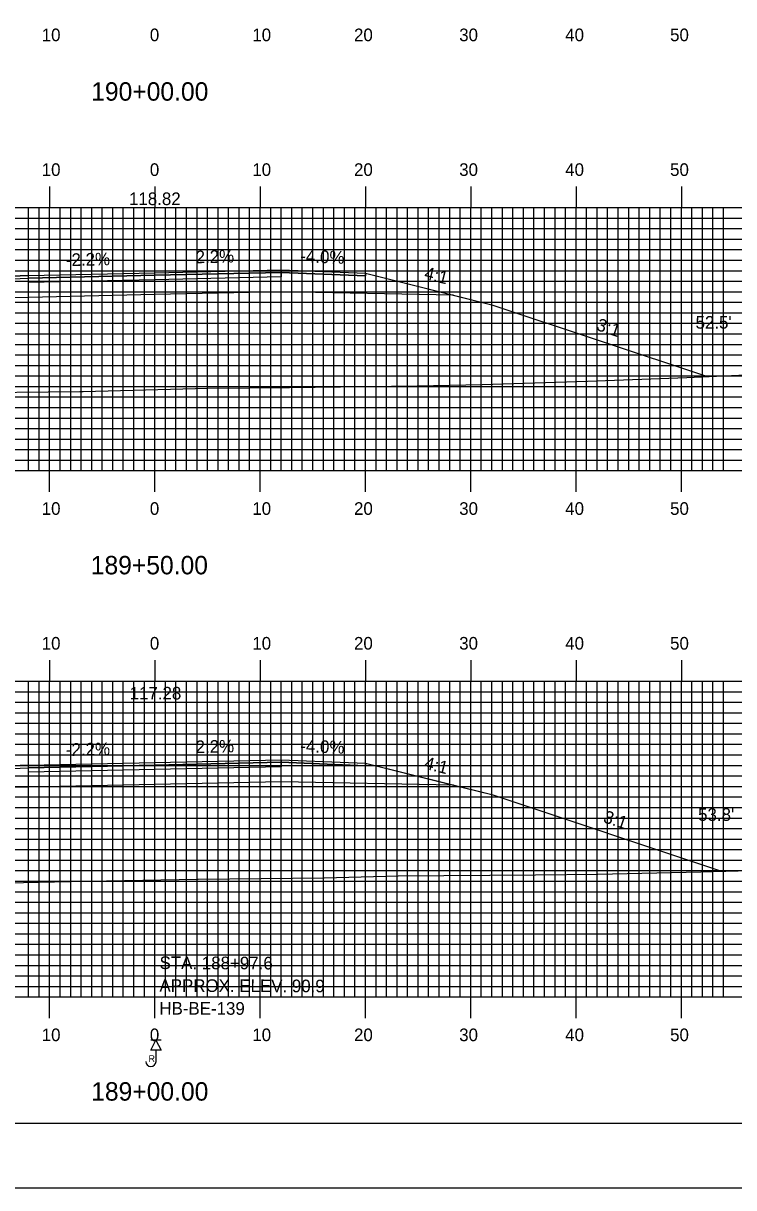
# Model space of a CAD drawing. Extents: x 1788156 to 1788500, y 442591 to 442811.
# Drawn here: x 1788309.6 to 1788377.1, y 442590.5 to 442701.2 of the extents above; entities that cross this region are included whole.
import ezdxf

# ---------------------------------------------------------------- set-up
doc = ezdxf.new("R2010")
doc.units = 0
for name, color, linetype in [('ANNOTATION', 7, 'Continuous'), ('BORDER', 7, 'Continuous'), ('BORING - NO REFUSAL', 7, 'Continuous'), ('BORING - REFUSAL', 7, 'Continuous'), ('D_Roadway_Centerline', 7, 'Continuous'), ('D_Roadway_Centerline_Text', 7, 'Continuous'), ('D_Roadway_Edge_Shoulder', 7, 'Continuous'), ('D_Roadway_Edge_TW', 7, 'Continuous'), ('D_Roadway_Pavement', 7, 'Continuous'), ('D_Roadway_SlopeLines', 7, 'Continuous'), ('D_Roadway_SubGrade', 7, 'Continuous'), ('D_Text_Standard', 7, 'Continuous'), ('H_V ANNOTATION', 7, 'Continuous'), ('MAJOR', 7, 'Continuous'), ('MINOR', 7, 'Continuous'), ('PLOT BOUNDARY', 7, 'Continuous'), ('S_Roadway_Centerline', 7, 'Continuous')]:
    doc.layers.add(name, color=color, linetype=linetype)

msp = doc.modelspace()

# ---------------------------------------------------------------- linework, layer by layer
at = {"layer": 'BORDER'}
msp.add_lwpolyline([(1788172.53, 442596.67), (1788492.53, 442596.67), (1788492.53, 442806.67), (1788172.53, 442806.67)], close=True, dxfattribs=at)
at = {"layer": 'BORING - NO REFUSAL'}
for p, q in [((1788322.71, 442604.57), (1788321.75, 442604.57)), ((1788322.23, 442603.61), (1788322.23, 442602.55))]:
    msp.add_line(p, q, dxfattribs=at)
msp.add_lwpolyline([(1788322.23, 442604.57), (1788322.71, 442603.61), (1788321.75, 442603.61)], close=True, dxfattribs=at)
msp.add_arc((1788321.75, 442602.55), 0.485, 180, 0, dxfattribs=at)
at = {"layer": 'D_Roadway_Centerline'}
for points in [[(1788265.27, 442665.61), (1788290.13, 442673.9), (1788293.77, 442674.81), (1788302.13, 442676.9), (1788310.13, 442677.22), (1788322.13, 442677.48), (1788334.13, 442677.75), (1788342.13, 442677.43), (1788350.49, 442675.33), (1788354.13, 442674.43), (1788374.61, 442667.6)], [(1788265.16, 442619.03), (1788290.13, 442627.36), (1788293.77, 442628.27), (1788302.13, 442630.36), (1788310.13, 442630.68), (1788322.13, 442630.94), (1788334.13, 442631.21), (1788342.13, 442630.89), (1788350.49, 442628.8), (1788354.13, 442627.89), (1788375.93, 442620.62)]]:
    msp.add_lwpolyline(points, dxfattribs=at)
at = {"layer": 'D_Roadway_Edge_Shoulder'}
for points in [[(1788310.13, 442677.22), (1788302.13, 442676.9), (1788302.13, 442676.65), (1788310.13, 442676.97)], [(1788334.13, 442677.75), (1788342.13, 442677.43), (1788342.13, 442677.18), (1788334.13, 442677.5)], [(1788310.13, 442630.68), (1788302.13, 442630.36), (1788302.13, 442630.11), (1788310.13, 442630.43)], [(1788334.13, 442631.21), (1788342.13, 442630.89), (1788342.13, 442630.64), (1788334.13, 442630.96)]]:
    msp.add_lwpolyline(points, close=True, dxfattribs=at)
at = {"layer": 'D_Roadway_Edge_TW'}
for points in [[(1788310.13, 442676.97), (1788310.13, 442677.22), (1788322.13, 442677.48), (1788334.13, 442677.75), (1788334.13, 442677.5), (1788322.13, 442677.23)], [(1788310.13, 442630.43), (1788310.13, 442630.68), (1788322.13, 442630.94), (1788334.13, 442631.21), (1788334.13, 442630.96), (1788322.13, 442630.69)]]:
    msp.add_lwpolyline(points, close=True, dxfattribs=at)
at = {"layer": 'D_Roadway_Pavement'}
for points in [[(1788310.13, 442676.55), (1788310.13, 442676.97), (1788322.13, 442677.23), (1788334.13, 442677.5), (1788334.13, 442677.08), (1788322.13, 442676.81)], [(1788310.13, 442630.01), (1788310.13, 442630.43), (1788322.13, 442630.69), (1788334.13, 442630.96), (1788334.13, 442630.54), (1788322.13, 442630.27)]]:
    msp.add_lwpolyline(points, close=True, dxfattribs=at)
at = {"layer": 'D_Roadway_SlopeLines'}
for points in [[(1788342.13, 442677.43), (1788354.13, 442674.43), (1788374.61, 442667.6)], [(1788342.13, 442630.89), (1788354.13, 442627.89), (1788375.93, 442620.62)]]:
    msp.add_lwpolyline(points, dxfattribs=at)
at = {"layer": 'D_Roadway_SubGrade'}
for points in [[(1788310.13, 442675.13), (1788293.77, 442674.81), (1788302.13, 442676.9), (1788302.13, 442676.65), (1788310.13, 442676.97), (1788322.13, 442677.23), (1788334.13, 442677.5), (1788342.13, 442677.18), (1788342.13, 442677.43), (1788350.49, 442675.33), (1788334.13, 442675.66), (1788322.13, 442675.4)], [(1788310.13, 442628.59), (1788293.77, 442628.27), (1788302.13, 442630.36), (1788302.13, 442630.11), (1788310.13, 442630.43), (1788322.13, 442630.69), (1788334.13, 442630.96), (1788342.13, 442630.64), (1788342.13, 442630.89), (1788350.49, 442628.8), (1788334.13, 442629.12), (1788322.13, 442628.86)]]:
    msp.add_lwpolyline(points, close=True, dxfattribs=at)
at = {"layer": 'MAJOR'}
for p, q in [((1788312.13, 442685.67), (1788312.13, 442683.67)), ((1788322.13, 442685.67), (1788322.13, 442683.67)), ((1788332.13, 442685.67), (1788332.13, 442683.67)), ((1788342.13, 442685.67), (1788342.13, 442683.67)), ((1788352.13, 442685.67), (1788352.13, 442683.67)), ((1788362.13, 442685.67), (1788362.13, 442683.67)), ((1788372.13, 442685.67), (1788372.13, 442683.67)), ((1788182.13, 442683.67), (1788462.13, 442683.67)), ((1788182.13, 442683.67), (1788462.13, 442683.67)), ((1788312.13, 442658.67), (1788312.13, 442683.67)), ((1788322.13, 442658.67), (1788322.13, 442683.67)), ((1788332.13, 442658.67), (1788332.13, 442683.67)), ((1788342.13, 442658.67), (1788342.13, 442683.67)), ((1788352.13, 442658.67), (1788352.13, 442683.67)), ((1788362.13, 442658.67), (1788362.13, 442683.67)), ((1788372.13, 442658.67), (1788372.13, 442683.67)), ((1788182.13, 442678.67), (1788462.13, 442678.67)), ((1788182.13, 442673.67), (1788462.13, 442673.67)), ((1788182.13, 442668.67), (1788462.13, 442668.67)), ((1788182.13, 442663.67), (1788462.13, 442663.67)), ((1788182.13, 442658.67), (1788462.13, 442658.67)), ((1788182.13, 442658.67), (1788462.13, 442658.67)), ((1788312.13, 442656.66), (1788312.13, 442658.67)), ((1788322.13, 442656.66), (1788322.13, 442658.67)), ((1788332.13, 442656.66), (1788332.13, 442658.67)), ((1788342.13, 442656.66), (1788342.13, 442658.67)), ((1788352.13, 442656.66), (1788352.13, 442658.67)), ((1788362.13, 442656.66), (1788362.13, 442658.67)), ((1788372.13, 442656.66), (1788372.13, 442658.67)), ((1788312.13, 442640.67), (1788312.13, 442638.67)), ((1788322.13, 442640.67), (1788322.13, 442638.67)), ((1788332.13, 442640.67), (1788332.13, 442638.67)), ((1788342.13, 442640.67), (1788342.13, 442638.67)), ((1788352.13, 442640.67), (1788352.13, 442638.67)), ((1788362.13, 442640.67), (1788362.13, 442638.67)), ((1788372.13, 442640.67), (1788372.13, 442638.67)), ((1788182.13, 442638.67), (1788462.13, 442638.67)), ((1788182.13, 442638.67), (1788462.13, 442638.67)), ((1788312.13, 442608.67), (1788312.13, 442638.67)), ((1788322.13, 442608.67), (1788322.13, 442638.67)), ((1788332.13, 442608.67), (1788332.13, 442638.67)), ((1788342.13, 442608.67), (1788342.13, 442638.67)), ((1788352.13, 442608.67), (1788352.13, 442638.67)), ((1788362.13, 442608.67), (1788362.13, 442638.67)), ((1788372.13, 442608.67), (1788372.13, 442638.67)), ((1788182.13, 442633.67), (1788462.13, 442633.67)), ((1788182.13, 442628.67), (1788462.13, 442628.67)), ((1788182.13, 442623.67), (1788462.13, 442623.67)), ((1788182.13, 442618.67), (1788462.13, 442618.67)), ((1788182.13, 442613.67), (1788462.13, 442613.67)), ((1788182.13, 442608.67), (1788462.13, 442608.67)), ((1788182.13, 442608.67), (1788462.13, 442608.67)), ((1788312.13, 442606.66), (1788312.13, 442608.67)), ((1788322.13, 442606.66), (1788322.13, 442608.67)), ((1788332.13, 442606.66), (1788332.13, 442608.67)), ((1788342.13, 442606.66), (1788342.13, 442608.67)), ((1788352.13, 442606.66), (1788352.13, 442608.67)), ((1788362.13, 442606.66), (1788362.13, 442608.67)), ((1788372.13, 442606.66), (1788372.13, 442608.67))]:
    msp.add_line(p, q, dxfattribs=at)
at = {"layer": 'MINOR'}
for p, q in [((1788310.13, 442658.67), (1788310.13, 442683.67)), ((1788311.13, 442658.67), (1788311.13, 442683.67)), ((1788313.13, 442658.67), (1788313.13, 442683.67)), ((1788314.13, 442658.67), (1788314.13, 442683.67)), ((1788315.13, 442658.67), (1788315.13, 442683.67)), ((1788316.13, 442658.67), (1788316.13, 442683.67)), ((1788317.13, 442658.67), (1788317.13, 442683.67)), ((1788318.13, 442658.67), (1788318.13, 442683.67)), ((1788319.13, 442658.67), (1788319.13, 442683.67)), ((1788320.13, 442658.67), (1788320.13, 442683.67)), ((1788321.13, 442658.67), (1788321.13, 442683.67)), ((1788323.13, 442658.67), (1788323.13, 442683.67)), ((1788324.13, 442658.67), (1788324.13, 442683.67)), ((1788325.13, 442658.67), (1788325.13, 442683.67)), ((1788326.13, 442658.67), (1788326.13, 442683.67)), ((1788327.13, 442658.67), (1788327.13, 442683.67)), ((1788328.13, 442658.67), (1788328.13, 442683.67)), ((1788329.13, 442658.67), (1788329.13, 442683.67)), ((1788330.13, 442658.67), (1788330.13, 442683.67)), ((1788331.13, 442658.67), (1788331.13, 442683.67)), ((1788333.13, 442658.67), (1788333.13, 442683.67)), ((1788334.13, 442658.67), (1788334.13, 442683.67)), ((1788335.13, 442658.67), (1788335.13, 442683.67)), ((1788336.13, 442658.67), (1788336.13, 442683.67)), ((1788337.13, 442658.67), (1788337.13, 442683.67)), ((1788338.13, 442658.67), (1788338.13, 442683.67)), ((1788339.13, 442658.67), (1788339.13, 442683.67)), ((1788340.13, 442658.67), (1788340.13, 442683.67)), ((1788341.13, 442658.67), (1788341.13, 442683.67)), ((1788343.13, 442658.67), (1788343.13, 442683.67)), ((1788344.13, 442658.67), (1788344.13, 442683.67)), ((1788345.13, 442658.67), (1788345.13, 442683.67)), ((1788346.13, 442658.67), (1788346.13, 442683.67)), ((1788347.13, 442658.67), (1788347.13, 442683.67)), ((1788348.13, 442658.67), (1788348.13, 442683.67)), ((1788349.13, 442658.67), (1788349.13, 442683.67)), ((1788350.13, 442658.67), (1788350.13, 442683.67)), ((1788351.13, 442658.67), (1788351.13, 442683.67)), ((1788353.13, 442658.67), (1788353.13, 442683.67)), ((1788354.13, 442658.67), (1788354.13, 442683.67)), ((1788355.13, 442658.67), (1788355.13, 442683.67)), ((1788356.13, 442658.67), (1788356.13, 442683.67)), ((1788357.13, 442658.67), (1788357.13, 442683.67)), ((1788358.13, 442658.67), (1788358.13, 442683.67)), ((1788359.13, 442658.67), (1788359.13, 442683.67)), ((1788360.13, 442658.67), (1788360.13, 442683.67)), ((1788361.13, 442658.67), (1788361.13, 442683.67)), ((1788363.13, 442658.67), (1788363.13, 442683.67)), ((1788364.13, 442658.67), (1788364.13, 442683.67)), ((1788365.13, 442658.67), (1788365.13, 442683.67)), ((1788366.13, 442658.67), (1788366.13, 442683.67)), ((1788367.13, 442658.67), (1788367.13, 442683.67)), ((1788368.13, 442658.67), (1788368.13, 442683.67)), ((1788369.13, 442658.67), (1788369.13, 442683.67)), ((1788370.13, 442658.67), (1788370.13, 442683.67)), ((1788371.13, 442658.67), (1788371.13, 442683.67)), ((1788373.13, 442658.67), (1788373.13, 442683.67)), ((1788374.13, 442658.67), (1788374.13, 442683.67)), ((1788375.13, 442658.67), (1788375.13, 442683.67)), ((1788376.13, 442658.67), (1788376.13, 442683.67)), ((1788182.13, 442682.67), (1788462.13, 442682.67)), ((1788182.13, 442681.67), (1788462.13, 442681.67)), ((1788182.13, 442680.67), (1788462.13, 442680.67)), ((1788182.13, 442679.67), (1788462.13, 442679.67)), ((1788182.13, 442677.67), (1788462.13, 442677.67)), ((1788182.13, 442676.67), (1788462.13, 442676.67)), ((1788182.13, 442675.67), (1788462.13, 442675.67)), ((1788182.13, 442674.67), (1788462.13, 442674.67)), ((1788182.13, 442672.67), (1788462.13, 442672.67)), ((1788182.13, 442671.67), (1788462.13, 442671.67)), ((1788182.13, 442670.67), (1788462.13, 442670.67)), ((1788182.13, 442669.67), (1788462.13, 442669.67)), ((1788182.13, 442667.67), (1788462.13, 442667.67)), ((1788182.13, 442666.67), (1788462.13, 442666.67)), ((1788182.13, 442665.67), (1788462.13, 442665.67)), ((1788182.13, 442664.67), (1788462.13, 442664.67)), ((1788182.13, 442662.67), (1788462.13, 442662.67)), ((1788182.13, 442661.67), (1788462.13, 442661.67)), ((1788182.13, 442660.67), (1788462.13, 442660.67)), ((1788182.13, 442659.67), (1788462.13, 442659.67)), ((1788310.13, 442608.67), (1788310.13, 442638.67)), ((1788311.13, 442608.67), (1788311.13, 442638.67)), ((1788313.13, 442608.67), (1788313.13, 442638.67)), ((1788314.13, 442608.67), (1788314.13, 442638.67)), ((1788315.13, 442608.67), (1788315.13, 442638.67)), ((1788316.13, 442608.67), (1788316.13, 442638.67)), ((1788317.13, 442608.67), (1788317.13, 442638.67)), ((1788318.13, 442608.67), (1788318.13, 442638.67)), ((1788319.13, 442608.67), (1788319.13, 442638.67)), ((1788320.13, 442608.67), (1788320.13, 442638.67)), ((1788321.13, 442608.67), (1788321.13, 442638.67)), ((1788323.13, 442608.67), (1788323.13, 442638.67)), ((1788324.13, 442608.67), (1788324.13, 442638.67)), ((1788325.13, 442608.67), (1788325.13, 442638.67)), ((1788326.13, 442608.67), (1788326.13, 442638.67)), ((1788327.13, 442608.67), (1788327.13, 442638.67)), ((1788328.13, 442608.67), (1788328.13, 442638.67)), ((1788329.13, 442608.67), (1788329.13, 442638.67)), ((1788330.13, 442608.67), (1788330.13, 442638.67)), ((1788331.13, 442608.67), (1788331.13, 442638.67)), ((1788333.13, 442608.67), (1788333.13, 442638.67)), ((1788334.13, 442608.67), (1788334.13, 442638.67)), ((1788335.13, 442608.67), (1788335.13, 442638.67)), ((1788336.13, 442608.67), (1788336.13, 442638.67)), ((1788337.13, 442608.67), (1788337.13, 442638.67)), ((1788338.13, 442608.67), (1788338.13, 442638.67)), ((1788339.13, 442608.67), (1788339.13, 442638.67)), ((1788340.13, 442608.67), (1788340.13, 442638.67)), ((1788341.13, 442608.67), (1788341.13, 442638.67)), ((1788343.13, 442608.67), (1788343.13, 442638.67)), ((1788344.13, 442608.67), (1788344.13, 442638.67)), ((1788345.13, 442608.67), (1788345.13, 442638.67)), ((1788346.13, 442608.67), (1788346.13, 442638.67)), ((1788347.13, 442608.67), (1788347.13, 442638.67)), ((1788348.13, 442608.67), (1788348.13, 442638.67)), ((1788349.13, 442608.67), (1788349.13, 442638.67)), ((1788350.13, 442608.67), (1788350.13, 442638.67)), ((1788351.13, 442608.67), (1788351.13, 442638.67)), ((1788353.13, 442608.67), (1788353.13, 442638.67)), ((1788354.13, 442608.67), (1788354.13, 442638.67)), ((1788355.13, 442608.67), (1788355.13, 442638.67)), ((1788356.13, 442608.67), (1788356.13, 442638.67)), ((1788357.13, 442608.67), (1788357.13, 442638.67)), ((1788358.13, 442608.67), (1788358.13, 442638.67)), ((1788359.13, 442608.67), (1788359.13, 442638.67)), ((1788360.13, 442608.67), (1788360.13, 442638.67)), ((1788361.13, 442608.67), (1788361.13, 442638.67)), ((1788363.13, 442608.67), (1788363.13, 442638.67)), ((1788364.13, 442608.67), (1788364.13, 442638.67)), ((1788365.13, 442608.67), (1788365.13, 442638.67)), ((1788366.13, 442608.67), (1788366.13, 442638.67)), ((1788367.13, 442608.67), (1788367.13, 442638.67)), ((1788368.13, 442608.67), (1788368.13, 442638.67)), ((1788369.13, 442608.67), (1788369.13, 442638.67)), ((1788370.13, 442608.67), (1788370.13, 442638.67)), ((1788371.13, 442608.67), (1788371.13, 442638.67)), ((1788373.13, 442608.67), (1788373.13, 442638.67)), ((1788374.13, 442608.67), (1788374.13, 442638.67)), ((1788375.13, 442608.67), (1788375.13, 442638.67)), ((1788376.13, 442608.67), (1788376.13, 442638.67)), ((1788182.13, 442637.67), (1788462.13, 442637.67)), ((1788182.13, 442636.67), (1788462.13, 442636.67)), ((1788182.13, 442635.67), (1788462.13, 442635.67)), ((1788182.13, 442634.67), (1788462.13, 442634.67)), ((1788182.13, 442632.67), (1788462.13, 442632.67)), ((1788182.13, 442631.67), (1788462.13, 442631.67)), ((1788182.13, 442630.67), (1788462.13, 442630.67)), ((1788182.13, 442629.67), (1788462.13, 442629.67)), ((1788182.13, 442627.67), (1788462.13, 442627.67)), ((1788182.13, 442626.67), (1788462.13, 442626.67)), ((1788182.13, 442625.67), (1788462.13, 442625.67)), ((1788182.13, 442624.67), (1788462.13, 442624.67)), ((1788182.13, 442622.67), (1788462.13, 442622.67)), ((1788182.13, 442621.67), (1788462.13, 442621.67)), ((1788182.13, 442620.67), (1788462.13, 442620.67)), ((1788182.13, 442619.67), (1788462.13, 442619.67)), ((1788182.13, 442617.67), (1788462.13, 442617.67)), ((1788182.13, 442616.67), (1788462.13, 442616.67)), ((1788182.13, 442615.67), (1788462.13, 442615.67)), ((1788182.13, 442614.67), (1788462.13, 442614.67)), ((1788182.13, 442612.67), (1788462.13, 442612.67)), ((1788182.13, 442611.67), (1788462.13, 442611.67)), ((1788182.13, 442610.67), (1788462.13, 442610.67)), ((1788182.13, 442609.67), (1788462.13, 442609.67))]:
    msp.add_line(p, q, dxfattribs=at)
at = {"layer": 'PLOT BOUNDARY'}
msp.add_lwpolyline([(1788156.34, 442590.55), (1788496.34, 442590.55), (1788496.34, 442810.55), (1788156.34, 442810.55)], close=True, dxfattribs=at)
at = {"layer": 'S_Roadway_Centerline'}
for points in [[(1788258.62, 442665.51), (1788267.31, 442665.64), (1788277.7, 442665.61), (1788281.73, 442665.66), (1788296.77, 442665.92), (1788302.97, 442666.05), (1788315, 442666.2), (1788315.2, 442666.2), (1788315.32, 442666.2), (1788327.17, 442666.51), (1788334.9, 442666.56), (1788347.04, 442666.73), (1788353.22, 442666.85), (1788363.21, 442667.18), (1788372.66, 442667.51), (1788379.02, 442667.79)], [(1788249.62, 442618.84), (1788262.21, 442619.01), (1788266.39, 442619.04), (1788268.95, 442619.09), (1788278.46, 442619.22), (1788287.81, 442619.35), (1788294.05, 442619.4), (1788306.66, 442619.47), (1788314.07, 442619.63), (1788326.15, 442619.87), (1788326.2, 442619.87), (1788326.24, 442619.87), (1788338.22, 442619.99), (1788345.23, 442620.17), (1788358.29, 442620.27), (1788364.21, 442620.32), (1788373.99, 442620.57), (1788383.47, 442620.81)]]:
    msp.add_lwpolyline(points, dxfattribs=at)

# ---------------------------------------------------------------- texts
at = {"layer": 'ANNOTATION'}
for s, rotation, p in [('-2.2%', 1.2603, (1788313.69, 442678.1)), ('2.2%', 1.2603, (1788326.01, 442678.37)), ('-4.0%', 357.7094, (1788335.92, 442678.48)), ('4:1', 345.9638, (1788347.64, 442676.91)), ('3:1', 341.5652, (1788363.98, 442672.05)), ('-2.2%', 1.2603, (1788313.69, 442631.56)), ('2.2%', 1.2603, (1788326.01, 442631.83)), ('-4.0%', 357.7094, (1788335.92, 442631.94)), ('4:1', 345.9638, (1788347.64, 442630.37)), ('3:1', 341.5652, (1788364.64, 442625.29))]:
    msp.add_text(s, height=1.2, rotation=rotation, dxfattribs=at).set_placement(p)
at = {"layer": 'BORING - NO REFUSAL'}
msp.add_text('R', height=0.64, dxfattribs=at).set_placement((1788321.52, 442602.49))
at = {"layer": 'BORING - REFUSAL'}
for s, p in [('STA. 188+97.6', (1788322.57, 442611.32)), ('APPROX. ELEV. 90.9', (1788322.56, 442609.16)), ('HB-BE-139', (1788322.55, 442607))]:
    msp.add_text(s, height=1.2, rotation=359.8142, dxfattribs=at).set_placement(p)
at = {"layer": 'D_Roadway_Centerline'}
for s, p in [('C', (1788322.13, 442677.48)), ('L', (1788322.13, 442677.47)), ('C', (1788322.13, 442630.94)), ('L', (1788322.13, 442630.93))]:
    msp.add_text(s, height=0.0146, dxfattribs=at).set_placement(p)
at = {"layer": 'D_Roadway_Centerline_Text'}
for s, p in [('118.82', (1788319.67, 442683.9)), ('117.28', (1788319.73, 442636.93))]:
    msp.add_text(s, height=1.2, dxfattribs=at).set_placement(p)
at = {"layer": 'D_Text_Standard'}
for s, p in [("52.5'", (1788373.48, 442672.16)), ("53.8'", (1788373.72, 442625.4))]:
    msp.add_text(s, height=1.2, dxfattribs=at).set_placement(p)
at = {"layer": 'H_V ANNOTATION'}
for s, height, p in [('10', 1.2, (1788311.38, 442699.47)), ('0', 1.2, (1788321.65, 442699.47)), ('10', 1.2, (1788331.38, 442699.47)), ('20', 1.2, (1788341.04, 442699.47)), ('30', 1.2, (1788351.03, 442699.47)), ('40', 1.2, (1788361.1, 442699.47)), ('50', 1.2, (1788371.06, 442699.47)), ('190+00.00', 1.75, (1788316.08, 442693.82)), ('10', 1.2, (1788311.38, 442686.67)), ('0', 1.2, (1788321.65, 442686.67)), ('10', 1.2, (1788331.38, 442686.67)), ('20', 1.2, (1788341.04, 442686.67)), ('30', 1.2, (1788351.03, 442686.67)), ('40', 1.2, (1788361.1, 442686.67)), ('50', 1.2, (1788371.06, 442686.67)), ('10', 1.2, (1788311.38, 442654.47)), ('0', 1.2, (1788321.65, 442654.47)), ('10', 1.2, (1788331.38, 442654.47)), ('20', 1.2, (1788341.04, 442654.47)), ('30', 1.2, (1788351.03, 442654.47)), ('40', 1.2, (1788361.1, 442654.47)), ('50', 1.2, (1788371.06, 442654.47)), ('189+50.00', 1.75, (1788316.04, 442648.82)), ('10', 1.2, (1788311.38, 442641.67)), ('0', 1.2, (1788321.65, 442641.67)), ('10', 1.2, (1788331.38, 442641.67)), ('20', 1.2, (1788341.04, 442641.67)), ('30', 1.2, (1788351.03, 442641.67)), ('40', 1.2, (1788361.1, 442641.67)), ('50', 1.2, (1788371.06, 442641.67)), ('10', 1.2, (1788311.38, 442604.47)), ('0', 1.2, (1788321.65, 442604.47)), ('10', 1.2, (1788331.38, 442604.47)), ('20', 1.2, (1788341.04, 442604.47)), ('30', 1.2, (1788351.03, 442604.47)), ('40', 1.2, (1788361.1, 442604.47)), ('50', 1.2, (1788371.06, 442604.47)), ('189+00.00', 1.75, (1788316.08, 442598.82))]:
    msp.add_text(s, height=height, dxfattribs=at).set_placement(p)

doc.saveas('drawing.dxf')
